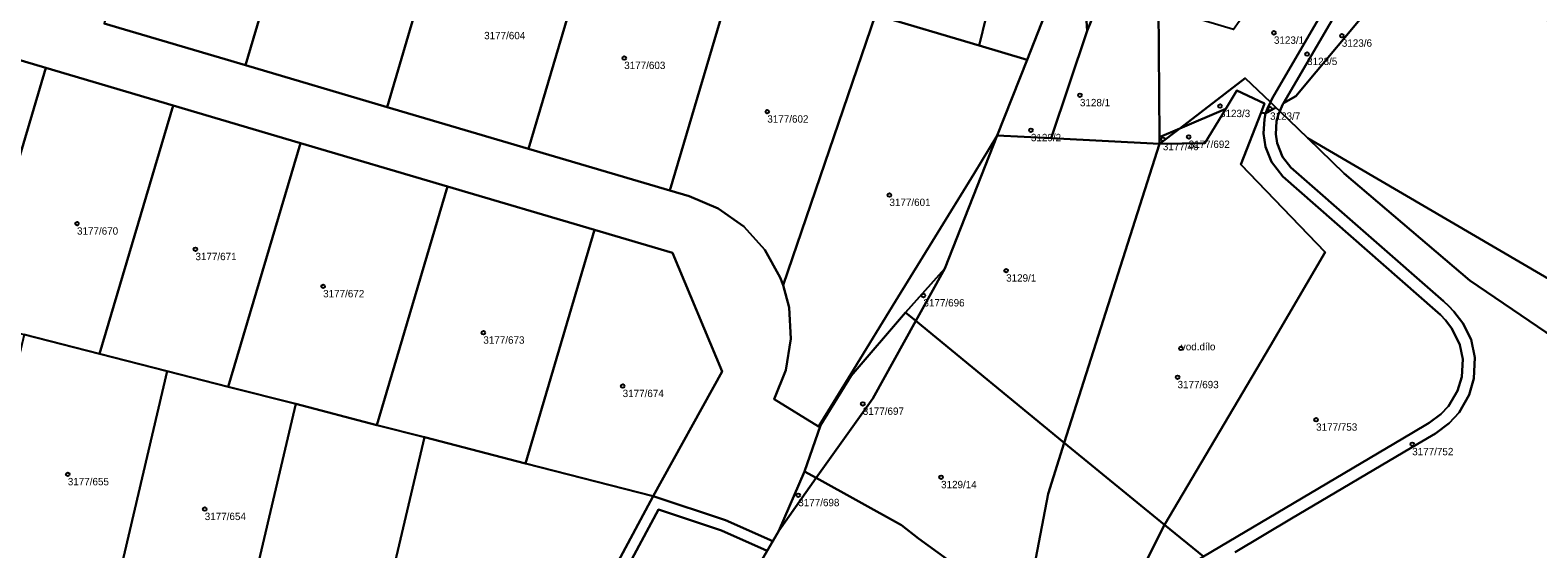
# Model space of a CAD drawing. Extents: x -878211 to -870363, y -1058464 to -1052522.
# Drawn here: x -874398.3 to -874193.8, y -1056850 to -1056779.6 of the extents above; entities that cross this region are included whole.
import ezdxf

# ---------------------------------------------------------------- set-up
doc = ezdxf.new("R2010")
doc.units = 0
doc.layers.add('Vrstva 50', color=7, linetype='Continuous')
doc.layers.add('Vrstva 51', color=7, linetype='Continuous')

msp = doc.modelspace()

# ---------------------------------------------------------------- linework, layer by layer
at = {"layer": 'Vrstva 50'}
for centre in [(-874229.63, -1056779.98994), (-874220.42, -1056780.38994), (-874317.72, -1056783.40994), (-874225.13, -1056782.86994), (-874255.93, -1056788.45994), (-874236.94, -1056789.92994), (-874298.32, -1056790.67994), (-874230.15, -1056790.28994), (-874262.58, -1056793.19994), (-874244.69, -1056794.41994), (-874241.19, -1056794.10994), (-874281.76, -1056801.98994), (-874391.91, -1056805.86994), (-874375.85, -1056809.32994), (-874265.94, -1056812.23994), (-874358.54, -1056814.36994), (-874277.15, -1056815.60994), (-874336.82, -1056820.65994), (-874242.25, -1056822.78994), (-874242.7, -1056826.69994), (-874317.93, -1056827.89994), (-874285.37, -1056830.30994), (-874223.91, -1056832.45994), (-874210.88, -1056835.78994), (-874393.16, -1056839.85994), (-874274.76, -1056840.25994), (-874294.12, -1056842.69994), (-874374.59, -1056844.57994)]:
    msp.add_circle(centre, 0.25, dxfattribs=at)
at = {"layer": 'Vrstva 51'}
for points in [[(-874379.53, -1056749.23), (-874388.24, -1056778.73), (-874369.06, -1056784.39), (-874360.35, -1056754.9), (-874364.86, -1056753.57)], [(-874360.35, -1056754.9), (-874369.06, -1056784.39), (-874349.88, -1056790.06), (-874341.17, -1056760.56), (-874349.03, -1056758.24)], [(-874341.17, -1056760.56), (-874349.88, -1056790.06), (-874330.7, -1056795.72), (-874321.99, -1056766.23), (-874333.32, -1056762.88)], [(-874233.51, -1056786.13), (-874230.11, -1056789.41), (-874229.86, -1056788.89), (-874220.36, -1056772.56), (-874218.47, -1056770.26), (-874216.45, -1056768.79), (-874215.2, -1056768.04), (-874223.76, -1056760.78), (-874227.42, -1056768.66), (-874235.1, -1056779.53), (-874245.27, -1056776.49), (-874245.16, -1056794.13), (-874242.38, -1056792.95)], [(-874285.93, -1056776.88), (-874283.63, -1056777.56), (-874269.6, -1056781.7), (-874266.74, -1056770.02), (-874282.75, -1056764.8)], [(-874321.99, -1056766.23), (-874330.7, -1056795.72), (-874311.52, -1056801.39), (-874302.81, -1056771.9), (-874317.6, -1056767.53)], [(-874230.11, -1056789.41), (-874229.37, -1056790.13), (-874228.85, -1056790.63), (-874228.42, -1056789.68), (-874228.33, -1056789.52), (-874218.99, -1056773.47), (-874217.42, -1056771.54), (-874215.83, -1056770.33), (-874213.87, -1056769.17), (-874215.2, -1056768.04), (-874216.45, -1056768.79), (-874218.47, -1056770.26), (-874220.36, -1056772.56), (-874229.86, -1056788.89)], [(-874211.74, -1056770.98), (-874213.87, -1056769.17), (-874215.83, -1056770.33), (-874217.42, -1056771.54), (-874218.99, -1056773.47), (-874228.33, -1056789.52), (-874226.68, -1056788.56), (-874215.43, -1056775.06)], [(-874263.09, -1056783.63), (-874258.7, -1056772.46), (-874266.74, -1056770.02), (-874269.6, -1056781.7)], [(-874302.81, -1056771.9), (-874311.52, -1056801.39), (-874308.92, -1056802.16), (-874304.98, -1056803.79), (-874301.5, -1056806.25), (-874298.65, -1056809.43), (-874296.57, -1056813.15), (-874296.16, -1056814.22), (-874283.63, -1056777.56), (-874285.93, -1056776.88), (-874301.89, -1056772.17)], [(-874267.14, -1056793.91), (-874259.84, -1056794.29), (-874254.95, -1056779.7), (-874255.35, -1056773.47), (-874258.7, -1056772.46), (-874263.09, -1056783.63)], [(-874259.84, -1056794.29), (-874245.15, -1056795.04), (-874245.16, -1056794.13), (-874245.27, -1056776.49), (-874252.73, -1056774.26), (-874254.95, -1056779.7)], [(-874254.95, -1056779.7), (-874252.73, -1056774.26), (-874255.35, -1056773.47)], [(-874283.63, -1056777.56), (-874296.16, -1056814.22), (-874295.37, -1056817.25), (-874295.11, -1056821.51), (-874295.79, -1056825.72), (-874297.39, -1056829.67), (-874291.39, -1056833.36), (-874286.6, -1056825.58), (-874280.94, -1056816.37), (-874275.56, -1056807.64), (-874270.28, -1056799.08), (-874267.14, -1056793.91), (-874263.09, -1056783.63), (-874269.6, -1056781.7)], [(-874406.29, -1056819.03), (-874396.15, -1056784.73), (-874413.41, -1056779.63), (-874423.73, -1056814.54), (-874416.5, -1056816.4)], [(-874388.84, -1056823.52), (-874378.88, -1056789.83), (-874396.15, -1056784.73), (-874406.29, -1056819.03), (-874399.06, -1056820.89)], [(-874230.78, -1056790.95), (-874230.5, -1056790.23), (-874230.11, -1056789.41), (-874233.51, -1056786.13), (-874242.38, -1056792.95), (-874236.17, -1056790.31), (-874234.65, -1056787.83), (-874230.9, -1056789.57), (-874231.38, -1056790.81)], [(-874234.13, -1056797.86), (-874231.38, -1056790.81), (-874230.9, -1056789.57), (-874234.65, -1056787.83), (-874236.17, -1056790.31), (-874239.02, -1056794.95), (-874245.15, -1056795.04), (-874258.05, -1056835.57), (-874244.49, -1056846.71), (-874230.12, -1056822.46), (-874222.67, -1056809.73)], [(-874229.37, -1056790.13), (-874230.11, -1056789.41), (-874230.5, -1056790.23), (-874230.78, -1056790.95)], [(-874371.4, -1056828.01), (-874361.62, -1056794.93), (-874378.88, -1056789.83), (-874388.84, -1056823.52), (-874379.69, -1056825.88)], [(-874239.02, -1056794.95), (-874236.17, -1056790.31), (-874242.38, -1056792.95), (-874245.15, -1056795.04)], [(-874204.17, -1056826.63), (-874204.04, -1056824.24), (-874204.42, -1056822.28), (-874205.49, -1056820.1), (-874206.37, -1056818.95), (-874207.05, -1056818.25), (-874207.78, -1056817.58), (-874228.42, -1056799.48), (-874229.97, -1056797.5), (-874230.78, -1056795.46), (-874231.05, -1056793.66), (-874230.9, -1056791.68), (-874230.78, -1056790.95), (-874231.38, -1056790.81), (-874234.13, -1056797.86), (-874222.67, -1056809.73), (-874230.12, -1056822.46), (-874244.49, -1056846.71), (-874239.16, -1056851.02), (-874235.74, -1056848.97), (-874228.1, -1056844.44), (-874210.93, -1056834.29), (-874208.57, -1056832.89), (-874206.99, -1056831.72), (-874205.98, -1056830.64), (-874204.74, -1056828.55)], [(-874245.15, -1056795.04), (-874242.38, -1056792.95), (-874245.16, -1056794.13)], [(-874351.27, -1056833.19), (-874341.69, -1056800.82), (-874361.62, -1056794.93), (-874371.4, -1056828.01), (-874362.24, -1056830.32)], [(-874245.15, -1056795.04), (-874259.84, -1056794.29), (-874267.14, -1056793.91), (-874274.25, -1056811.97), (-874278.18, -1056819.04), (-874258.05, -1056835.57)], [(-874049.34, -1056914.15), (-874014.23, -1056932.75), (-874007.51, -1056921.23), (-874042.84, -1056899.69), (-874076.67, -1056880.17), (-874135.18, -1056846.79), (-874225.05, -1056794.29), (-874220.11, -1056799.06), (-874203.06, -1056813.57), (-874129.69, -1056863.48), (-874108.33, -1056874.46), (-874102.53, -1056878.64), (-874078.93, -1056895.35), (-874073.45, -1056899.05), (-874056.93, -1056909.47)], [(-874321.77, -1056806.7), (-874341.69, -1056800.82), (-874351.27, -1056833.19), (-874344.81, -1056834.81), (-874331.1, -1056838.38)], [(-874313.81, -1056842.83), (-874304.46, -1056825.93), (-874311.19, -1056809.83), (-874321.77, -1056806.7), (-874331.1, -1056838.38)], [(-874278.18, -1056819.04), (-874274.25, -1056811.97), (-874279.57, -1056817.9)], [(-874293.29, -1056839.46), (-874291.68, -1056840.36), (-874284.03, -1056829.56), (-874278.18, -1056819.04), (-874279.57, -1056817.9), (-874286.95, -1056826.5), (-874291.09, -1056833.26)], [(-874277.8, -1056848.56), (-874263.42, -1056859.02), (-874260.25, -1056842.49), (-874258.05, -1056835.57), (-874278.18, -1056819.04), (-874284.03, -1056829.56), (-874291.68, -1056840.36), (-874280.13, -1056846.78)], [(-874399.06, -1056820.89), (-874406.94, -1056854.5), (-874387.47, -1056859.06), (-874379.69, -1056825.88), (-874388.84, -1056823.52)], [(-874362.24, -1056830.32), (-874371.4, -1056828.01), (-874379.69, -1056825.88), (-874387.47, -1056859.06), (-874369.95, -1056863.17)], [(-874344.81, -1056834.81), (-874351.27, -1056833.19), (-874362.24, -1056830.32), (-874369.95, -1056863.17), (-874352.42, -1056867.28)], [(-874331.1, -1056838.38), (-874344.81, -1056834.81), (-874352.42, -1056867.28), (-874347.63, -1056868.34), (-874347.46, -1056867.6), (-874335.28, -1056870.46), (-874333.15, -1056870.76), (-874331.03, -1056870.34), (-874329.17, -1056869.26), (-874327.77, -1056867.62), (-874321.52, -1056855.97), (-874321, -1056856.25), (-874313.81, -1056842.83)], [(-874246.96, -1056851.65), (-874244.49, -1056846.71), (-874258.05, -1056835.57), (-874260.25, -1056842.49), (-874263.42, -1056859.02), (-874260.17, -1056861.38), (-874259.1, -1056860.81), (-874252.81, -1056857.48)], [(-874275.99, -1056874.59), (-874271.46, -1056876.89), (-874264.29, -1056863.56), (-874263.42, -1056859.02), (-874277.8, -1056848.56), (-874280.13, -1056846.78), (-874291.68, -1056840.36), (-874296.77, -1056847.54), (-874297.57, -1056848.92), (-874298.32, -1056850.23), (-874299.77, -1056852.73), (-874302.89, -1056863.3), (-874290.78, -1056871.09), (-874289.16, -1056867.72)], [(-874293.29, -1056839.46), (-874296.77, -1056847.54), (-874291.68, -1056840.36)], [(-874299.77, -1056852.73), (-874298.32, -1056850.23), (-874304.54, -1056847.49), (-874313.08, -1056844.65), (-874325.9, -1056868.56), (-874329.74, -1056872.15), (-874333.7, -1056872.54), (-874336.17, -1056881.74), (-874336.38, -1056888.11), (-874335.86, -1056886.26), (-874335.54, -1056884.28), (-874335.73, -1056882.32), (-874330.78, -1056872.53), (-874329.39, -1056872.14), (-874328.12, -1056871.27), (-874326.94, -1056869.74), (-874316.75, -1056875.42), (-874315.05, -1056876.49), (-874313.75, -1056877.06), (-874313.62, -1056876.68)], [(-874259.1, -1056860.81), (-874259.81, -1056863.37), (-874239.16, -1056851.02), (-874244.49, -1056846.71), (-874246.96, -1056851.65), (-874252.81, -1056857.48)]]:
    msp.add_lwpolyline(points, close=True, dxfattribs=at)
for points in [[(-874130.88, -1056818.38), (-874200.78, -1056772.92), (-874208.8, -1056767.72), (-874211.74, -1056770.98), (-874215.43, -1056775.06), (-874226.68, -1056788.56), (-874228.33, -1056789.52), (-874228.42, -1056789.68), (-874228.85, -1056790.63), (-874225.05, -1056794.29), (-874135.18, -1056846.79)], [(-874413.41, -1056779.63), (-874396.15, -1056784.73), (-874378.88, -1056789.83), (-874361.62, -1056794.93), (-874341.69, -1056800.82), (-874321.77, -1056806.7), (-874311.19, -1056809.83), (-874304.46, -1056825.93), (-874313.81, -1056842.83), (-874304, -1056846.09), (-874297.57, -1056848.92), (-874296.77, -1056847.54), (-874293.29, -1056839.46), (-874291.09, -1056833.26), (-874286.95, -1056826.5), (-874279.57, -1056817.9), (-874274.25, -1056811.97), (-874267.14, -1056793.91), (-874270.28, -1056799.08), (-874275.56, -1056807.64), (-874280.94, -1056816.37), (-874286.6, -1056825.58), (-874291.39, -1056833.36), (-874297.39, -1056829.67), (-874295.79, -1056825.72), (-874295.11, -1056821.51), (-874295.37, -1056817.25), (-874296.16, -1056814.22), (-874296.57, -1056813.15), (-874298.65, -1056809.43), (-874301.5, -1056806.25), (-874304.98, -1056803.79), (-874308.92, -1056802.16), (-874311.52, -1056801.39), (-874330.7, -1056795.72), (-874349.88, -1056790.06), (-874369.06, -1056784.39), (-874388.24, -1056778.73)], [(-874234.9, -1056850.4), (-874227.26, -1056845.87), (-874210.1, -1056835.73), (-874207.73, -1056834.31), (-874205.86, -1056832.94), (-874204.53, -1056831.46), (-874203.18, -1056829.08), (-874202.53, -1056826.86), (-874202.41, -1056824.03), (-874202.91, -1056821.57), (-874204.01, -1056819.35), (-874205.22, -1056817.78), (-874205.9, -1056817.08), (-874206.63, -1056816.4), (-874227.33, -1056798.25), (-874228.48, -1056796.79), (-874229.2, -1056794.94), (-874229.38, -1056793.71), (-874229.28, -1056791.99), (-874229.02, -1056791.02), (-874228.85, -1056790.63), (-874229.37, -1056790.13), (-874230.78, -1056790.95), (-874230.9, -1056791.68), (-874231.05, -1056793.66), (-874230.78, -1056795.46), (-874229.97, -1056797.5), (-874228.42, -1056799.48), (-874207.78, -1056817.58), (-874207.05, -1056818.25), (-874206.37, -1056818.95), (-874205.49, -1056820.1), (-874204.42, -1056822.28), (-874204.04, -1056824.24), (-874204.17, -1056826.63), (-874204.74, -1056828.55), (-874205.98, -1056830.64), (-874206.99, -1056831.72), (-874208.57, -1056832.89), (-874210.93, -1056834.29), (-874228.1, -1056844.44), (-874235.74, -1056848.97), (-874239.16, -1056851.02)], [(-874129.69, -1056863.48), (-874203.06, -1056813.57), (-874220.11, -1056799.06), (-874225.05, -1056794.29), (-874228.85, -1056790.63), (-874229.02, -1056791.02), (-874229.28, -1056791.99), (-874229.38, -1056793.71), (-874229.2, -1056794.94), (-874228.48, -1056796.79), (-874227.33, -1056798.25), (-874206.63, -1056816.4), (-874205.9, -1056817.08), (-874205.22, -1056817.78), (-874204.01, -1056819.35), (-874202.91, -1056821.57), (-874202.41, -1056824.03), (-874202.53, -1056826.86), (-874203.18, -1056829.08), (-874204.53, -1056831.46), (-874205.86, -1056832.94), (-874207.73, -1056834.31), (-874210.1, -1056835.73), (-874227.26, -1056845.87), (-874234.9, -1056850.4)], [(-874325.9, -1056868.56), (-874313.08, -1056844.65), (-874304.54, -1056847.49), (-874298.32, -1056850.23), (-874297.57, -1056848.92), (-874304, -1056846.09), (-874313.81, -1056842.83), (-874321, -1056856.25)]]:
    msp.add_lwpolyline(points, dxfattribs=at)

# ---------------------------------------------------------------- texts
at = {"layer": 'Vrstva 50'}
for s, p in [('3177/604', (-874336.71, -1056780.859)), ('3123/1', (-874229.63, -1056781.479)), ('3123/6', (-874220.42, -1056781.879)), ('3123/5', (-874225.13, -1056784.359)), ('3177/603', (-874317.72, -1056784.899)), ('3128/1', (-874255.93, -1056789.949)), ('3177/602', (-874298.32, -1056792.169)), ('3123/3', (-874236.94, -1056791.419)), ('3123/7', (-874230.15, -1056791.779)), ('3129/2', (-874262.58, -1056794.689)), ('3177/46', (-874244.69, -1056795.909)), ('3177/692', (-874241.19, -1056795.599)), ('3177/601', (-874281.76, -1056803.479)), ('3177/670', (-874391.91, -1056807.359)), ('3177/671', (-874375.85, -1056810.819)), ('3129/1', (-874265.94, -1056813.729)), ('3177/672', (-874358.54, -1056815.859)), ('3177/696', (-874277.15, -1056817.099)), ('3177/673', (-874336.82, -1056822.149)), ('vod.dílo', (-874242.25, -1056823.04)), ('3177/674', (-874317.93, -1056829.389)), ('3177/693', (-874242.7, -1056828.189)), ('3177/697', (-874285.37, -1056831.799)), ('3177/753', (-874223.91, -1056833.949)), ('3177/752', (-874210.88, -1056837.279)), ('3177/655', (-874393.16, -1056841.349)), ('3129/14', (-874274.76, -1056841.749)), ('3177/698', (-874294.12, -1056844.189)), ('3177/654', (-874374.59, -1056846.069))]:
    msp.add_text(s, height=0.999996, dxfattribs=at).set_placement(p)

doc.saveas('drawing.dxf')
